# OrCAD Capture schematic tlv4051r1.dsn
size A
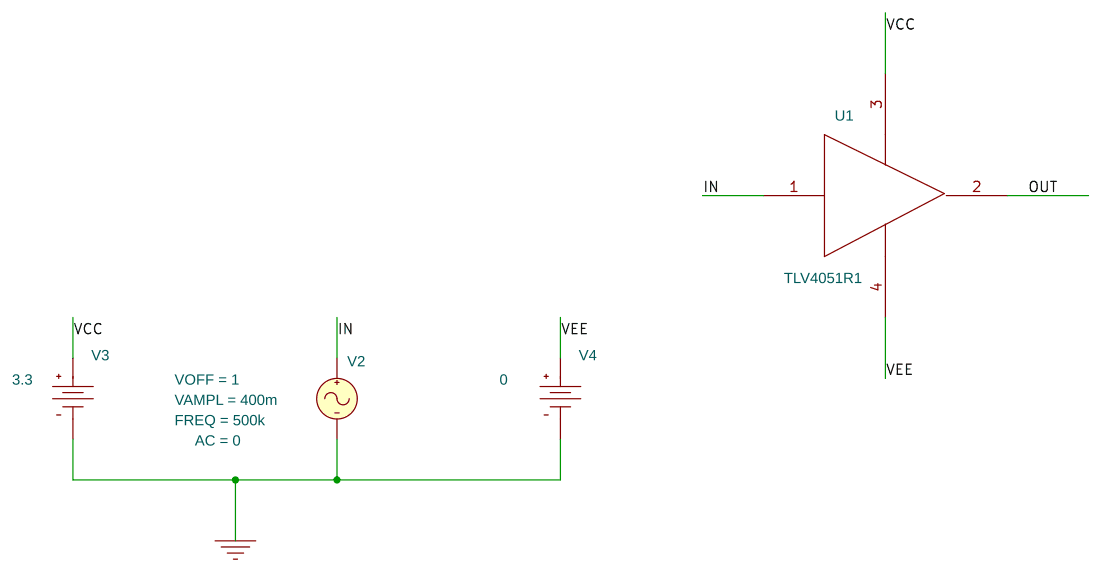
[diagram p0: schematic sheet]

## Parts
U1  TLV4051R1
V2  VSIN
V3  VDC
V4  VDC

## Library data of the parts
U1 = TLV4051R1_2
V2 = VSIN: AC: 0; AppProp: Sine$Voltage$0$-1; DC: 0; FREQ: 500k; VAMPL: 400m; VOFF: 1
V3 = VDC: AppProp: DC$Voltage$0$-1; DC: 3.3
V4 = VDC: AppProp: DC$Voltage$0$-1; DC: 0

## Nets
VCC: U1.3(VCC) V3.0(+)
VEE: U1.4(VEE) V4.0(+)
0: V2.2(-) V3.1(-) V4.1(-)
IN: U1.1(IN) V2.1(+)
OUT: U1.2(OUT)
